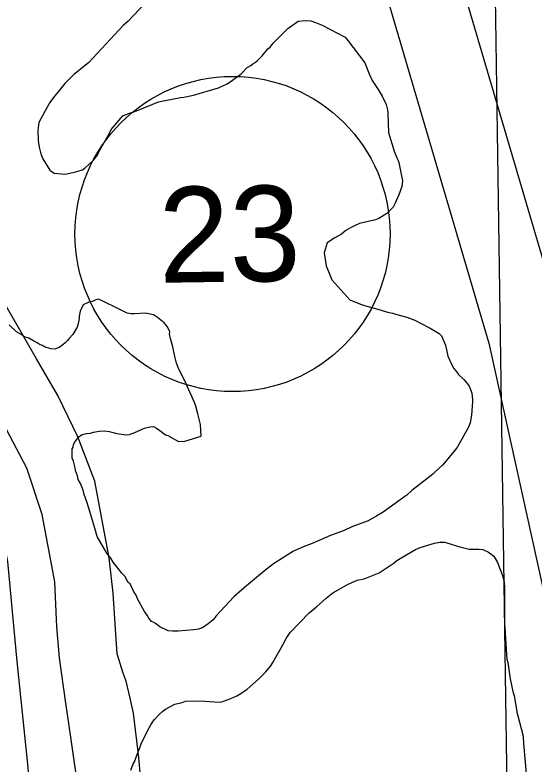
# Model space of a CAD drawing. Extents: x 3812694 to 3850888, y 319753 to 345638.
# Drawn here: x 3826791 to 3827334, y 341766 to 342550 of the extents above; entities that cross this region are included whole.
import ezdxf

# ---------------------------------------------------------------- set-up
doc = ezdxf.new("R2010")
doc.units = 0
for name, color, linetype in [('V-GRID-MAJR', 7, 'Continuous'), ('V-LEVE-TOET', 7, 'Continuous'), ('V-ROAD-CNTR', 7, 'Continuous'), ('V-ROAD-IDEN', 7, 'Continuous'), ('V-SITE-VEGE', 7, 'Continuous'), ('V-TOPO-SHOR', 7, 'Continuous')]:
    doc.layers.add(name, color=color, linetype=linetype)

msp = doc.modelspace()

# ---------------------------------------------------------------- linework, layer by layer
at = {"layer": 'V-GRID-MAJR'}
msp.add_spline([(3827552.137, 325339.081), (3827461.389, 331396.12), (3827370.595, 337456.243), (3827279.801, 343516.363), (3827279.755, 343519.449)], degree=3, dxfattribs=at)
at = {"layer": 'V-LEVE-TOET'}
msp.add_lwpolyline([(3826772.2770000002, 342027.244), (3826782.8850000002, 341977.789), (3826792.501, 341873.202), (3826803.664, 341765.451), (3826816.096, 341621.452), (3826831.79, 341490.554), (3826851.506, 341338.617), (3826865.35, 341175.7), (3826877.575, 341068.989)], dxfattribs=at)
at = {"layer": 'V-ROAD-CNTR'}
for points in [[(3826888.6931831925, 343517.1919401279), (3827149.466661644, 342673.62762726), (3827287.1033863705, 342206.556561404), (3827360.534239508, 341872.6532292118), (3827388.635183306, 341707.0015605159), (3827434.7350911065, 341341.6672911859), (3827456.3330479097, 341039.02889646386), (3827475.617009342, 340587.6007993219), (3827499.9879606, 340026.6819211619), (3827519.2949219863, 339556.0618624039), (3827541.499877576, 339155.85566281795), (3827581.6147973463, 338852.35326982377), (3827660.2136401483, 338530.8169128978), (3827812.32233593, 338143.5096875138), (3827979.35200187, 337772.53642946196), (3828135.815688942, 337439.2100961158), (3828238.825482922, 337215.3125439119)], [(3826963.79903298, 343518.32793785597), (3827224.645511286, 342696.6345812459), (3827363.29323399, 342226.1345222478), (3827437.725085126, 341887.67919915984), (3827466.4240277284, 341718.50253751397), (3827512.999934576, 341349.39227573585), (3827534.829890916, 341043.50588750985), (3827554.160852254, 340590.98479255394), (3827578.534803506, 340029.9989145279), (3827597.821764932, 339559.850854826), (3827619.8297209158, 339163.19464813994), (3827658.994642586, 338866.8802407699), (3827735.3244899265, 338554.6278652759), (3827884.7961909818, 338174.0346264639), (3828050.78185901, 337805.37936377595), (3828207.1095463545, 337472.34302985), (3828311.024338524, 337246.47848158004)]]:
    msp.add_lwpolyline(points, dxfattribs=at)
at = {"layer": 'V-ROAD-IDEN'}
msp.add_circle((3827018.525761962, 342320.71212670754), 164.99966999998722, dxfattribs=at)
at = {"layer": 'V-SITE-VEGE'}
for p, q in [((3826937.991, 342574.23600000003), (3826909.253, 342543.50599999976)), ((3826904.16, 342538.925), (3826867.542, 342499.939)), ((3826909.253, 342543.50599999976), (3826904.16, 342538.925)), ((3827076.524, 342535.70900000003), (3827087.167, 342543.4919999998)), ((3827087.167, 342543.4919999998), (3827094.548, 342544.37499999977)), ((3827094.548, 342544.37499999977), (3827100.534, 342543.88300000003)), ((3827100.534, 342543.88300000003), (3827105.595, 342542.011)), ((3827105.595, 342542.011), (3827112.4930000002, 342539.2099999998)), ((3827112.4930000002, 342539.2099999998), (3827136.395, 342526.64099999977)), ((3827061.233, 342520.583), (3827076.524, 342535.70900000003)), ((3827136.395, 342526.64099999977), (3827139.143, 342523.39899999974)), ((3827139.143, 342523.39899999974), (3827156.994, 342499.798)), ((3827055.671, 342514.619), (3827057.985, 342516.452)), ((3827057.985, 342516.452), (3827061.233, 342520.583)), ((3827044.544, 342502.235), (3827049.642, 342507.277)), ((3827049.642, 342507.277), (3827055.671, 342514.619)), ((3826867.542, 342499.939), (3826852.2660000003, 342487.575)), ((3827039.918, 342499.03), (3827042.23, 342500.40199999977)), ((3827042.23, 342500.40199999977), (3827044.544, 342502.235)), ((3827156.994, 342499.798), (3827161.542, 342488.251)), ((3827027.419, 342488.49700000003), (3827033.9050000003, 342494.915)), ((3827033.9050000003, 342494.915), (3827037.603, 342497.20099999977)), ((3827037.603, 342497.20099999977), (3827039.918, 342499.03)), ((3826852.2660000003, 342487.575), (3826842.998, 342478.4059999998)), ((3827018.622, 342481.6299999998), (3827027.419, 342488.49700000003)), ((3827161.542, 342488.251), (3827164.733, 342481.32099999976)), ((3826842.998, 342478.4059999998), (3826830.938, 342463.7199999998)), ((3827003.836, 342473.87200000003), (3827013.074, 342477.97000000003)), ((3827013.074, 342477.97000000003), (3827018.622, 342481.63)), ((3827164.733, 342481.32099999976), (3827171.137, 342472.0699999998)), ((3826977.521, 342466.17600000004), (3827003.836, 342473.87200000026)), ((3827171.137, 342472.0699999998), (3827175.2490000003, 342465.13300000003)), ((3826830.938, 342463.7199999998), (3826827.223, 342458.20900000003)), ((3826941.073, 342458.991), (3826964.14, 342463.4809999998)), ((3826964.14, 342463.4809999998), (3826967.369, 342463.9229999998)), ((3826967.369, 342463.923), (3826977.521, 342466.17600000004)), ((3827175.2490000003, 342465.13300000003), (3827179.352, 342456.3559999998)), ((3826824.433, 342453.613), (3826815.59, 342437.52799999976)), ((3826827.223, 342458.20900000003), (3826824.433, 342453.613)), ((3826916.128, 342448.9829999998), (3826935.068, 342456.71799999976)), ((3826935.068, 342456.718), (3826941.073, 342458.991)), ((3827179.352, 342456.3559999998), (3827180.703, 342450.818)), ((3826891.603, 342430.2149999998), (3826903.66, 342444.44)), ((3826903.66, 342444.44), (3826909.665, 342446.71399999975)), ((3826909.665, 342446.71399999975), (3826916.128, 342448.9829999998)), ((3827180.703, 342450.818), (3827181.148, 342447.588)), ((3827181.148, 342447.588), (3827181.961, 342426.84399999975)), ((3826815.59, 342437.52799999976), (3826814.625, 342429.2379999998)), ((3826814.625, 342429.2379999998), (3826815.031, 342418.6339999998)), ((3826890.203, 342426.99599999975), (3826891.603, 342430.2149999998)), ((3826878.1070000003, 342405.8579999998), (3826886.946, 342421.482)), ((3826886.946, 342421.482), (3826890.203, 342426.99599999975)), ((3827181.961, 342426.84399999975), (3827182.866, 342423.61)), ((3827182.866, 342423.61), (3827187.8510000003, 342407.451)), ((3826815.031, 342418.6339999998), (3826815.916, 342411.715)), ((3826815.916, 342411.715), (3826817.724, 342404.7929999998)), ((3826877.171, 342403.097), (3826878.1070000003, 342405.8579999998)), ((3827187.8510000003, 342407.451), (3827190.579, 342400.525)), ((3826817.724, 342404.7929999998), (3826819.997, 342399.249)), ((3826819.997, 342399.249), (3826827.313, 342387.688)), ((3826863.734, 342389.802), (3826872.997, 342398.049)), ((3826872.997, 342398.049), (3826877.171, 342403.097)), ((3827190.579, 342400.525), (3827191.949, 342397.75199999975)), ((3827191.949, 342397.75199999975), (3827192.856, 342395.44199999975)), ((3826860.9590000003, 342387.973), (3826863.734, 342389.802)), ((3827192.856, 342395.44199999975), (3827196.4420000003, 342376.52699999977)), ((3826827.313, 342387.688), (3826831.904, 342384.438)), ((3826831.904, 342384.438), (3826843.42, 342383.455)), ((3826843.42, 342383.455), (3826854.4960000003, 342385.702)), ((3826854.4960000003, 342385.702), (3826860.9590000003, 342387.973)), ((3827196.4420000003, 342376.52699999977), (3827195.953, 342370.5359999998)), ((3827195.953, 342370.5359999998), (3827192.68, 342361.79499999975)), ((3827192.68, 342361.79499999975), (3827188.48, 342352.139)), ((3827188.48, 342352.139), (3827186.62, 342348.924)), ((3827186.62, 342348.924), (3827180.13, 342342.04399999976)), ((3827168.112, 342335.6549999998), (3827151.501, 342331.59399999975)), ((3827171.809, 342337.01900000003), (3827168.112, 342335.6549999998)), ((3827180.13, 342342.04399999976), (3827171.809, 342337.0189999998)), ((3827142.256, 342327.033), (3827137.173, 342324.29399999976)), ((3827146.881, 342329.775), (3827142.256, 342327.033)), ((3827151.501, 342331.59399999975), (3827146.881, 342329.775)), ((3827132.545, 342320.63300000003), (3827125.61, 342316.52)), ((3827137.173, 342324.29399999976), (3827132.545, 342320.63299999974)), ((3827117.7460000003, 342311.4879999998), (3827114.465, 342300.908)), ((3827125.61, 342316.52), (3827117.7460000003, 342311.4879999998)), ((3827114.465, 342300.908), (3827116.699, 342287.52899999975)), ((3827116.699, 342287.52899999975), (3827120.3340000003, 342277.831)), ((3827120.3340000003, 342277.831), (3827122.614, 342272.7479999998)), ((3827122.614, 342272.7479999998), (3827141.4, 342251.90999999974)), ((3826868.066, 342249.2), (3826862.057, 342246.4659999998)), ((3826871.758, 342250.102), (3826868.066, 342249.2)), ((3826875.457, 342251.92599999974), (3826871.758, 342250.102)), ((3826878.222, 342252.373), (3826875.457, 342251.92600000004)), ((3826882.8200000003, 342250.505), (3826878.222, 342252.373)), ((3826898.45, 342242.58699999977), (3826882.8200000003, 342250.505)), ((3827141.4, 342251.90999999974), (3827152.4390000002, 342247.243)), ((3826862.057, 342246.4659999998), (3826858.799, 342240.029)), ((3826908.1040000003, 342237.92600000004), (3826898.45, 342242.58699999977)), ((3827152.4390000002, 342247.243), (3827156.58, 342245.838)), ((3827156.58, 342245.838), (3827173.146, 342241.142)), ((3827173.146, 342241.142), (3827180.97, 342238.795)), ((3826857.846, 342234.504), (3826857.8340000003, 342232.2)), ((3826858.799, 342240.029), (3826857.846, 342234.504)), ((3826912.247, 342236.9819999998), (3826908.1040000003, 342237.92600000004)), ((3826915.936, 342236.964), (3826912.247, 342236.9819999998)), ((3826927.464, 342237.826), (3826915.936, 342236.964)), ((3826935.748, 342235.9379999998), (3826927.464, 342237.826)), ((3826939.883, 342233.1499999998), (3826935.748, 342235.9379999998)), ((3826946.7660000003, 342227.58399999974), (3826939.883, 342233.1499999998)), ((3827180.97, 342238.795), (3827186.495, 342237.844)), ((3827186.495, 342237.844), (3827189.256, 342236.91000000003)), ((3827189.256, 342236.91000000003), (3827201.222, 342233.617)), ((3827201.222, 342233.617), (3827209.502, 342230.347)), ((3826792.312, 342218.25699999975), (3826784.5160000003, 342225.6729999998)), ((3826856.8880000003, 342227.135), (3826855.944, 342222.992)), ((3826857.8340000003, 342232.2), (3826856.8880000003, 342227.135)), ((3826948.6010000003, 342225.72999999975), (3826946.7660000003, 342227.58399999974)), ((3826950.432, 342223.4159999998), (3826948.6010000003, 342225.72999999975)), ((3827209.502, 342230.347), (3827214.559, 342227.5550000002)), ((3827214.559, 342227.55499999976), (3827225.591, 342221.966)), ((3826797.826, 342215.00099999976), (3826792.312, 342218.25699999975)), ((3826855.944, 342222.992), (3826851.295, 342215.642)), ((3826952.71, 342218.33299999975), (3826950.432, 342223.4159999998)), ((3826952.697, 342216.02899999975), (3826952.71, 342218.33299999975)), ((3827225.591, 342221.966), (3827231.565, 342218.71)), ((3827231.565, 342218.71), (3827234.779, 342216.387)), ((3826801.041, 342212.681), (3826797.826, 342215.00099999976)), ((3826805.182, 342211.73600000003), (3826801.041, 342212.681)), ((3826811.156, 342208.01699999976), (3826805.182, 342211.73600000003)), ((3826845.73, 342209.217), (3826843.414, 342206.92600000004)), ((3826847.123, 342211.05599999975), (3826845.73, 342209.217)), ((3826851.295, 342215.642), (3826847.123, 342211.05599999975)), ((3826953.596, 342211.415), (3826952.697, 342216.02899999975)), ((3826955.853, 342202.64299999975), (3826953.596, 342211.415)), ((3827234.779, 342216.38699999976), (3827237.5330000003, 342214.0689999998)), ((3827237.5330000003, 342214.0689999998), (3827241.629, 342204.368)), ((3826813.915, 342206.61999999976), (3826811.156, 342208.01699999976)), ((3826817.13, 342204.7589999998), (3826813.915, 342206.61999999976)), ((3826819.43, 342203.8249999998), (3826817.13, 342204.7589999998)), ((3826821.728, 342202.42999999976), (3826819.43, 342203.8249999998)), ((3826828.171, 342200.5519999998), (3826821.728, 342202.42999999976)), ((3826836.934, 342201.89), (3826832.316, 342200.071)), ((3826840.637, 342204.63599999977), (3826836.934, 342201.8899999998)), ((3826843.414, 342206.92599999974), (3826840.637, 342204.63599999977)), ((3826958.1040000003, 342192.493), (3826955.853, 342202.64299999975)), ((3827241.629, 342204.368), (3827243.8740000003, 342192.835)), ((3826832.316, 342200.071), (3826828.171, 342200.5519999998)), ((3826959.912, 342185.571), (3826958.1040000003, 342192.493)), ((3826962.184, 342179.106), (3826959.912, 342185.571)), ((3827243.8740000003, 342192.835), (3827248.433, 342183.13)), ((3826968.573, 342167.0899999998), (3826962.184, 342179.106)), ((3827248.433, 342183.13), (3827250.257, 342179.89400000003)), ((3827250.257, 342179.89400000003), (3827253.923, 342175.726)), ((3827253.923, 342175.726), (3827254.8370000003, 342173.877)), ((3827254.8370000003, 342173.877), (3827260.798, 342168.317)), ((3826971.3030000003, 342160.62199999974), (3826968.573, 342167.0899999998)), ((3827260.798, 342168.317), (3827263.088, 342165.538)), ((3827263.088, 342165.538), (3827266.293, 342161.37200000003)), ((3826978.592, 342144.451), (3826971.3030000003, 342160.62199999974)), ((3827266.293, 342161.37200000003), (3827268.571, 342156.2909999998)), ((3827268.571, 342156.2909999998), (3827269.019, 342153.985)), ((3827269.019, 342153.985), (3827269.9080000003, 342147.527)), ((3827269.9080000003, 342147.527), (3827269.896, 342145.221)), ((3826979.954, 342140.29600000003), (3826978.592, 342144.451)), ((3826982.217, 342132.44599999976), (3826979.954, 342140.29600000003)), ((3827269.896, 342145.221), (3827268.898, 342130.939)), ((3826984.9250000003, 342121.37200000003), (3826982.217, 342132.44599999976)), ((3827268.898, 342130.939), (3827267.475, 342123.11100000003)), ((3827267.475, 342123.11100000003), (3827265.605, 342118.51099999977)), ((3826916.204, 342112.978), (3826923.134, 342116.166)), ((3826923.134, 342116.166), (3826926.3680000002, 342117.5319999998)), ((3826926.3680000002, 342117.5319999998), (3826932.367, 342118.8839999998)), ((3826932.367, 342118.8839999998), (3826935.597, 342119.3239999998)), ((3826935.597, 342119.324), (3826938.8140000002, 342117.4669999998)), ((3826938.8140000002, 342117.4669999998), (3826942.488, 342115.142)), ((3826942.488, 342115.142), (3826948.454, 342110.50199999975)), ((3826985.781, 342108.923), (3826984.9250000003, 342121.37200000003)), ((3827265.605, 342118.51099999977), (3827253.975, 342097.83299999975)), ((3826855.323, 342105.462), (3826856.255, 342107.30099999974)), ((3826856.255, 342107.30099999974), (3826860.421, 342110.50599999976)), ((3826860.421, 342110.506), (3826865.498, 342111.862)), ((3826865.498, 342111.862), (3826869.649, 342112.29999999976)), ((3826869.649, 342112.29999999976), (3826872.881, 342113.205)), ((3826872.881, 342113.205), (3826878.875, 342114.096)), ((3826878.875, 342114.096), (3826884.87, 342114.52399999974)), ((3826884.87, 342114.52399999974), (3826889.478, 342114.039)), ((3826889.478, 342114.039), (3826897.301, 342111.694)), ((3826897.301, 342111.694), (3826907.432, 342110.25800000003)), ((3826907.432, 342110.25799999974), (3826910.66, 342110.6999999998)), ((3826910.66, 342110.7), (3826916.204, 342112.978)), ((3826948.454, 342110.50199999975), (3826950.756, 342109.5679999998)), ((3826950.756, 342109.568), (3826961.784, 342103.518)), ((3826968.7, 342103.9439999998), (3826985.781, 342108.923)), ((3826851.596, 342097.64799999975), (3826852.069, 342099.94799999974)), ((3826852.069, 342099.94799999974), (3826853.003, 342102.248)), ((3826853.003, 342102.248), (3826855.323, 342105.462)), ((3826961.784, 342103.518), (3826968.7, 342103.9439999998)), ((3826850.613, 342086.1279999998), (3826850.664, 342095.8069999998)), ((3826850.664, 342095.8069999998), (3826851.596, 342097.64799999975)), ((3827252.117, 342095.076), (3827238.666, 342079.01599999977)), ((3827253.975, 342097.83299999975), (3827252.117, 342095.076)), ((3826851.9790000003, 342082.8949999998), (3826850.613, 342086.1279999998)), ((3826853.333, 342077.357), (3826851.9790000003, 342082.8949999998)), ((3826854.2320000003, 342073.204), (3826853.333, 342077.357)), ((3827238.666, 342079.01599999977), (3827230.791, 342071.6819999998)), ((3826856.046, 342067.664), (3826854.2320000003, 342073.204)), ((3827228.475, 342069.38799999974), (3827206.258, 342051.99)), ((3827230.791, 342071.6819999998), (3827228.475, 342069.38799999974)), ((3826856.947, 342063.51), (3826856.046, 342067.664)), ((3826859.231, 342059.351), (3826856.947, 342063.51)), ((3826861.9590000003, 342052.422), (3826859.231, 342059.351)), ((3826863.3170000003, 342047.804), (3826861.9590000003, 342052.422)), ((3826866.044, 342040.417), (3826863.3170000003, 342047.804)), ((3827198.853, 342046.039), (3827176.181, 342029.56499999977)), ((3827201.165, 342047.40899999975), (3827198.853, 342046.039)), ((3827206.258, 342051.99), (3827201.165, 342047.40899999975)), ((3826867.859, 342034.8729999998), (3826866.044, 342040.417)), ((3826874.193, 342012.7199999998), (3826867.859, 342034.8729999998)), ((3827176.181, 342029.56499999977), (3827169.708, 342025.45199999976)), ((3827169.708, 342025.45199999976), (3827160.463, 342020.43099999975)), ((3827143.3740000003, 342014.068), (3827135.518, 342010.42)), ((3827160.463, 342020.431), (3827143.3740000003, 342014.068)), ((3826876.913, 342003.946), (3826874.193, 342012.7199999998)), ((3827135.518, 342010.42), (3827121.203, 342004.966)), ((3826886.961, 341986.3789999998), (3826876.913, 342003.946)), ((3827121.203, 342004.966), (3827101.802, 341996.77)), ((3827093.487, 341993.588), (3827082.399, 341988.57599999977)), ((3827101.802, 341996.77), (3827093.487, 341993.588)), ((3826891.079, 341981.28499999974), (3826886.961, 341986.3789999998)), ((3827082.399, 341988.57599999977), (3827061.59, 341975.319)), ((3826893.365, 341977.1279999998), (3826891.079, 341981.28499999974)), ((3826898.862, 341970.6459999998), (3826893.365, 341977.1279999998)), ((3827061.59, 341975.319), (3827051.872, 341967.996)), ((3826902.521, 341965.5569999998), (3826898.862, 341970.6459999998)), ((3827051.872, 341967.996), (3827031.04, 341950.592)), ((3826905.733, 341962.3129999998), (3826902.521, 341965.5569999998)), ((3826909.384, 341955.841), (3826905.733, 341962.3129999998)), ((3826911.221, 341954.45), (3826909.384, 341955.841)), ((3826914.867, 341946.59399999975), (3826911.221, 341954.45)), ((3827031.04, 341950.592), (3827019.9250000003, 341940.968)), ((3826916.241, 341944.7429999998), (3826914.867, 341946.59399999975)), ((3826918.0700000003, 341941.968), (3826916.241, 341944.7429999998)), ((3826918.975, 341938.738), (3826918.0700000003, 341941.968)), ((3826926.278, 341925.332), (3826918.975, 341938.738)), ((3827019.9250000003, 341940.968), (3827001.382, 341920.787)), ((3826929.025, 341921.6289999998), (3826926.278, 341925.332)), ((3826930.8510000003, 341918.39299999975), (3826929.025, 341921.6289999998)), ((3827001.382, 341920.787), (3826998.134, 341916.656)), ((3826933.6, 341915.15299999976), (3826930.8510000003, 341918.39299999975)), ((3826935.4390000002, 341914.21899999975), (3826933.6, 341915.15299999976)), ((3826937.735, 341912.827), (3826935.4390000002, 341914.21899999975)), ((3826942.326, 341909.577), (3826937.735, 341912.827)), ((3826993.043, 341912.536), (3826987.0300000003, 341908.419)), ((3826998.134, 341916.656), (3826993.043, 341912.536)), ((3826951.063, 341905.382), (3826942.326, 341909.577)), ((3826955.669, 341904.89699999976), (3826951.063, 341905.382)), ((3826961.661, 341904.86399999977), (3826955.669, 341904.89699999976)), ((3826977.798, 341906.162), (3826961.661, 341904.864)), ((3826982.875, 341907.0569999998), (3826977.798, 341906.1619999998)), ((3826987.0300000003, 341908.419), (3826982.875, 341907.05700000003))]:
    msp.add_line(p, q, dxfattribs=at)
msp.add_lwpolyline([(3826912.038, 341759.479), (3826914.377, 341765.917), (3826915.774, 341768.215), (3826919.045, 341776.958), (3826920.91, 341781.093), (3826922.784, 341787.075), (3826929.305, 341799.949), (3826933.028, 341806.841), (3826935.353, 341810.517), (3826936.7460000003, 341812.352), (3826941.38, 341817.398), (3826945.5500000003, 341821.064), (3826948.327, 341823.354), (3826958.032, 341828.373), (3826965.876, 341830.17600000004), (3826969.11, 341831.542), (3826983.862, 341831.925), (3826989.389, 341831.433), (3827004.596, 341830.43200000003), (3827007.363, 341830.878), (3827012.907, 341833.153), (3827016.599, 341834.517), (3827023.069, 341837.249), (3827027.228, 341839.531), (3827033.704, 341844.106), (3827046.2090000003, 341855.102), (3827053.1580000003, 341861.979), (3827058.722, 341868.404), (3827060.586, 341872.08), (3827071.2830000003, 341890.46), (3827074.545, 341897.356), (3827078.725, 341903.326), (3827098.6520000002, 341923.964), (3827106.523, 341930.376), (3827116.7090000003, 341939.537), (3827123.65, 341945.034), (3827131.512, 341949.601), (3827138.91, 341953.711), (3827149.074, 341958.264), (3827156.453, 341959.609), (3827172.159, 341965.98), (3827181.412, 341972.385), (3827187.884, 341976.499), (3827190.663, 341978.789), (3827201.761, 341985.643), (3827210.082, 341990.208), (3827215.165, 341992.488), (3827229.937, 341997.018), (3827235.473, 341997.911), (3827240.544, 341997.884), (3827242.846, 341997.411), (3827256.649, 341993.19), (3827266.318, 341990.835), (3827276.455, 341990.782), (3827280.603, 341990.298), (3827286.579, 341987.503), (3827292.088, 341983.325), (3827296.202, 341976.849), (3827301.199, 341962.99700000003), (3827303.0100000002, 341956.533), (3827303.436, 341950.08), (3827303.237, 341912.286), (3827303.68, 341908.596), (3827304.9390000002, 341885.543), (3827305.807, 341875.397), (3827306.713, 341872.168), (3827309.389, 341855.10000000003), (3827312.085, 341841.718), (3827313.4420000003, 341837.102), (3827316.572, 341818.64900000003), (3827317.481, 341816.339), (3827322.447, 341796.494), (3827322.894, 341793.727), (3827323.3200000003, 341787.272), (3827325.921, 341755.915)], dxfattribs=at)
at = {"layer": 'V-TOPO-SHOR'}
for points in [[(3826903.953, 341860.744), (3826897.844, 341881.185), (3826896.441, 341901.587), (3826893.654, 341944.745), (3826889.2460000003, 341981.642), (3826874.21, 342061.757), (3826856.548, 342108.173), (3826835.724, 342151.476), (3826813.292, 342190.087), (3826766.108, 342271.249)], [(3826837.1780000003, 341876.94), (3826834.696, 341909.515), (3826832.33, 341956.607), (3826819.1720000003, 342026.927), (3826803.091, 342075.69800000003), (3826777.98, 342123.363)], [(3826938.562, 341030.911), (3826927.597, 341157.291), (3826909.5500000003, 341278.733), (3826895.061, 341391.287), (3826890.205, 341488.09), (3826884.4760000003, 341535.837), (3826873.6040000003, 341619.512), (3826858.4220000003, 341730.71), (3826849.191, 341793.93200000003), (3826844.043, 341829.41000000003), (3826837.1780000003, 341876.94)], [(3826941.411, 341537.443), (3826938.294, 341544.738), (3826934.921, 341548.854), (3826928.398, 341556.403), (3826926.665, 341566.414), (3826927.865, 341573.897), (3826932.578, 341593.847), (3826934.603, 341618.586), (3826928.123, 341684.509), (3826920.241, 341772.705), (3826914.727, 341818.86), (3826911.457, 341834.788), (3826907.0640000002, 341852.542), (3826903.953, 341860.744)]]:
    msp.add_lwpolyline(points, dxfattribs=at)

# ---------------------------------------------------------------- texts
at = {"layer": 'V-ROAD-IDEN'}
msp.add_text('23', height=99.9996340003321, rotation=0.8434804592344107, dxfattribs=at).set_placement((3826941.7109155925, 342269.57622897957))

doc.saveas('drawing.dxf')
